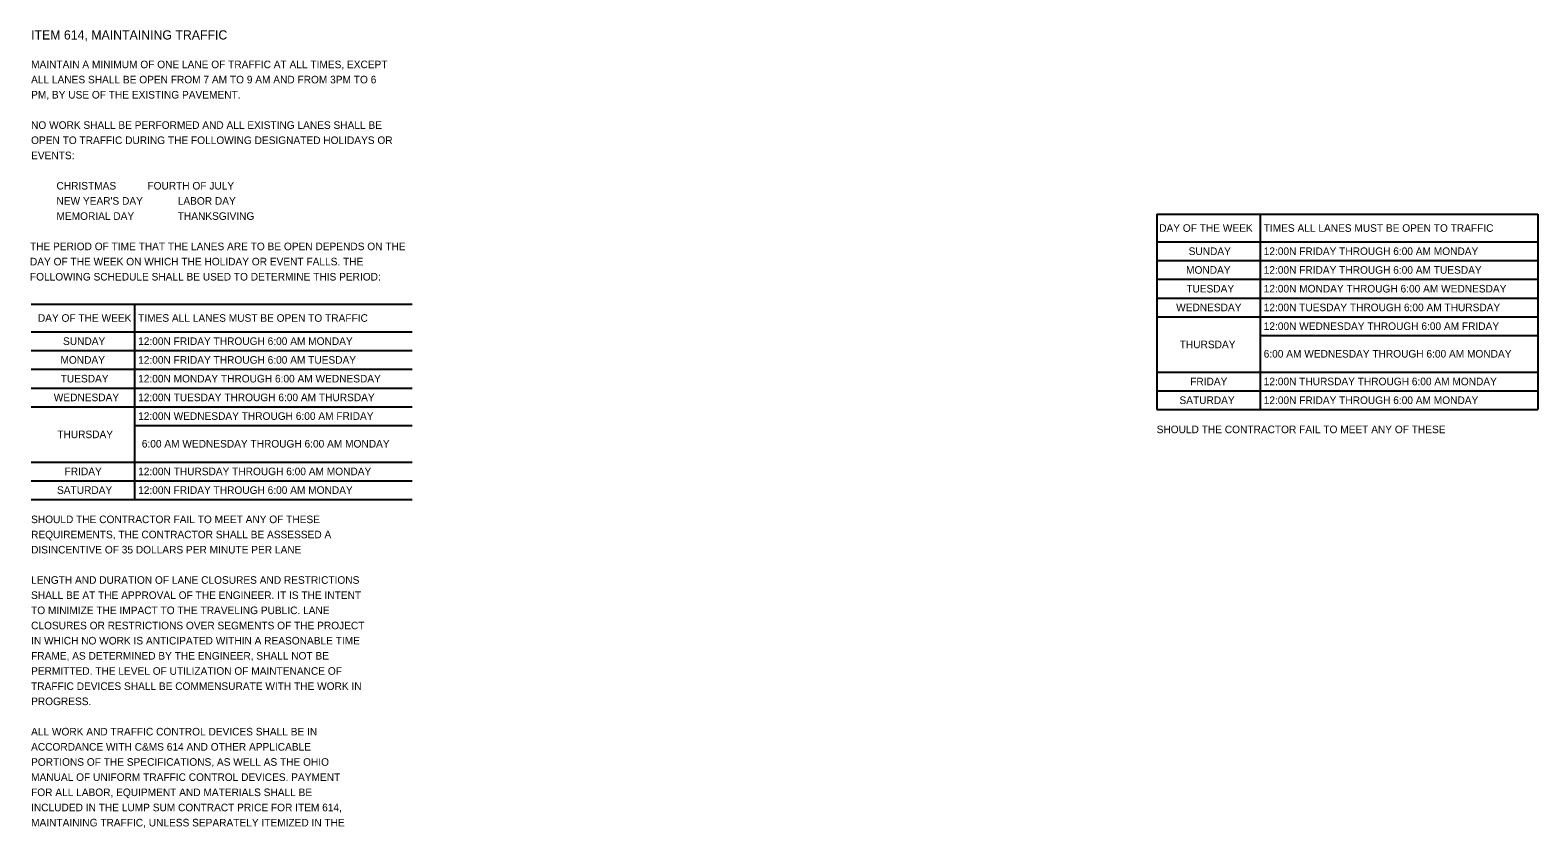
# Model space of a CAD drawing. Extents: x -57 to 90, y -15 to 48.
# Drawn here: x -29.92 to -2.07, y 4.75 to 19.48 of the extents above; entities that cross this region are included whole.
import ezdxf

# ---------------------------------------------------------------- set-up
doc = ezdxf.new("R2010")
doc.units = 0
doc.layers.add('SH_Data', color=7, linetype='Continuous')
doc.layers.add('SH_Text', color=7, linetype='Continuous')

msp = doc.modelspace()

# ---------------------------------------------------------------- linework, layer by layer
at = {"layer": 'SH_Data'}
for p, q in [((-9.111, 16.084), (-2.07, 16.084)), ((-9.111, 16.084), (-9.111, 12.476)), ((-7.2, 16.084), (-7.2, 12.476)), ((-2.07, 16.084), (-2.07, 12.476)), ((-9.111, 15.573), (-2.07, 15.573)), ((-9.111, 15.227), (-2.07, 15.227)), ((-9.111, 14.881), (-2.07, 14.881)), ((-9.111, 14.535), (-2.07, 14.535)), ((-29.903, 14.423), (-22.862, 14.423)), ((-27.992, 14.423), (-27.992, 10.816)), ((-27.992, 14.423), (-27.992, 10.816)), ((-9.111, 14.189), (-2.07, 14.189)), ((-29.903, 13.912), (-22.862, 13.912)), ((-29.903, 13.912), (-22.862, 13.912)), ((-7.2, 13.844), (-2.07, 13.844)), ((-29.903, 13.566), (-22.862, 13.566)), ((-29.903, 13.566), (-22.862, 13.566)), ((-29.903, 13.22), (-22.862, 13.22)), ((-29.903, 13.22), (-22.862, 13.22)), ((-9.111, 13.168), (-2.07, 13.168)), ((-29.903, 12.874), (-22.862, 12.874)), ((-29.903, 12.874), (-22.862, 12.874)), ((-9.111, 12.822), (-2.07, 12.822)), ((-29.903, 12.529), (-22.862, 12.529)), ((-29.903, 12.529), (-22.862, 12.529)), ((-9.111, 12.476), (-2.07, 12.476)), ((-27.992, 12.183), (-22.862, 12.183)), ((-27.992, 12.183), (-22.862, 12.183)), ((-29.903, 11.507), (-22.862, 11.507)), ((-29.903, 11.507), (-22.862, 11.507)), ((-29.903, 11.161), (-22.862, 11.161)), ((-29.903, 11.161), (-22.862, 11.161)), ((-29.903, 10.816), (-22.862, 10.816)), ((-29.903, 10.816), (-22.862, 10.816))]:
    msp.add_line(p, q, dxfattribs=at)

# ---------------------------------------------------------------- texts
at = {"layer": 'SH_Text'}
for s, height, p in [('ITEM 614, MAINTAINING TRAFFIC', 0.17, (-29.903, 19.309)), ('MAINTAIN A MINIMUM OF ONE LANE OF TRAFFIC AT ALL TIMES, EXCEPT ', 0.14, (-29.903, 18.779)), ('ALL LANES SHALL BE OPEN FROM 7 AM TO 9 AM AND FROM 3PM TO 6 ', 0.14, (-29.903, 18.499)), ('PM, BY USE OF THE EXISTING PAVEMENT.', 0.14, (-29.903, 18.219)), ('NO WORK SHALL BE PERFORMED AND ALL EXISTING LANES SHALL BE ', 0.14, (-29.903, 17.659)), ('OPEN TO TRAFFIC DURING THE FOLLOWING DESIGNATED HOLIDAYS OR ', 0.14, (-29.903, 17.379)), ('EVENTS:', 0.14, (-29.903, 17.099)), ('CHRISTMAS', 0.14, (-29.434, 16.539)), ('FOURTH OF JULY', 0.14, (-27.754, 16.539)), ("NEW YEAR'S DAY", 0.14, (-29.434, 16.259)), ('LABOR DAY', 0.14, (-27.194, 16.259)), ('MEMORIAL DAY', 0.14, (-29.434, 15.979)), ('THANKSGIVING', 0.14, (-27.194, 15.979)), ('DAY OF THE WEEK', 0.14, (-9.064, 15.758)), ('TIMES ALL LANES MUST BE OPEN TO TRAFFIC', 0.14, (-7.134, 15.758)), ('THE PERIOD OF TIME THAT THE LANES ARE TO BE OPEN DEPENDS ON THE ', 0.14, (-29.924, 15.419)), ('SUNDAY', 0.14, (-8.521, 15.33)), ('12:00N FRIDAY THROUGH 6:00 AM MONDAY', 0.14, (-7.134, 15.33)), ('DAY OF THE WEEK ON WHICH THE HOLIDAY OR EVENT FALLS. THE ', 0.14, (-29.924, 15.139)), ('MONDAY', 0.14, (-8.568, 14.984)), ('12:00N FRIDAY THROUGH 6:00 AM TUESDAY', 0.14, (-7.134, 14.984)), ('FOLLOWING SCHEDULE SHALL BE USED TO DETERMINE THIS PERIOD:', 0.14, (-29.924, 14.859)), ('TUESDAY', 0.14, (-8.564, 14.638)), ('12:00N MONDAY THROUGH 6:00 AM WEDNESDAY', 0.14, (-7.134, 14.638)), ('DAY OF THE WEEK', 0.14, (-29.777, 14.097)), ('TIMES ALL LANES MUST BE OPEN TO TRAFFIC', 0.14, (-27.926, 14.097)), ('WEDNESDAY', 0.14, (-8.751, 14.292)), ('12:00N TUESDAY THROUGH 6:00 AM THURSDAY', 0.14, (-7.134, 14.292)), ('12:00N WEDNESDAY THROUGH 6:00 AM FRIDAY', 0.14, (-7.134, 13.946)), ('SUNDAY', 0.14, (-29.313, 13.669)), ('12:00N FRIDAY THROUGH 6:00 AM MONDAY', 0.14, (-27.926, 13.669)), ('THURSDAY', 0.14, (-8.685, 13.609)), ('MONDAY', 0.14, (-29.36, 13.323)), ('12:00N FRIDAY THROUGH 6:00 AM TUESDAY', 0.14, (-27.926, 13.323)), ('6:00 AM WEDNESDAY THROUGH 6:00 AM MONDAY', 0.14, (-7.134, 13.436)), ('TUESDAY', 0.14, (-29.356, 12.977)), ('12:00N MONDAY THROUGH 6:00 AM WEDNESDAY', 0.14, (-27.926, 12.977)), ('FRIDAY', 0.14, (-8.492, 12.925)), ('12:00N THURSDAY THROUGH 6:00 AM MONDAY', 0.14, (-7.134, 12.925)), ('WEDNESDAY', 0.14, (-29.484, 12.631)), ('12:00N TUESDAY THROUGH 6:00 AM THURSDAY', 0.14, (-27.926, 12.631)), ('SATURDAY', 0.14, (-8.69, 12.579)), ('12:00N FRIDAY THROUGH 6:00 AM MONDAY', 0.14, (-7.134, 12.579)), ('12:00N WEDNESDAY THROUGH 6:00 AM FRIDAY', 0.14, (-27.926, 12.286)), ('THURSDAY', 0.14, (-29.419, 11.948)), ('SHOULD THE CONTRACTOR FAIL TO MEET ANY OF THESE', 0.14, (-9.111, 12.04)), ('6:00 AM WEDNESDAY THROUGH 6:00 AM MONDAY', 0.14, (-27.858, 11.775)), ('FRIDAY', 0.14, (-29.284, 11.264)), ('12:00N THURSDAY THROUGH 6:00 AM MONDAY', 0.14, (-27.926, 11.264)), ('SATURDAY', 0.14, (-29.424, 10.919)), ('12:00N FRIDAY THROUGH 6:00 AM MONDAY', 0.14, (-27.926, 10.919)), ('SHOULD THE CONTRACTOR FAIL TO MEET ANY OF THESE', 0.14, (-29.903, 10.379)), ('REQUIREMENTS, THE CONTRACTOR SHALL BE ASSESSED A', 0.14, (-29.903, 10.099)), ('DISINCENTIVE OF 35 DOLLARS PER MINUTE PER LANE', 0.14, (-29.903, 9.819)), ('LENGTH AND DURATION OF LANE CLOSURES AND RESTRICTIONS', 0.14, (-29.903, 9.259)), ('SHALL BE AT THE APPROVAL OF THE ENGINEER. IT IS THE INTENT', 0.14, (-29.903, 8.979)), ('TO MINIMIZE THE IMPACT TO THE TRAVELING PUBLIC. LANE', 0.14, (-29.903, 8.699)), ('CLOSURES OR RESTRICTIONS OVER SEGMENTS OF THE PROJECT', 0.14, (-29.903, 8.419)), ('IN WHICH NO WORK IS ANTICIPATED WITHIN A REASONABLE TIME', 0.14, (-29.903, 8.139)), ('FRAME, AS DETERMINED BY THE ENGINEER, SHALL NOT BE', 0.14, (-29.903, 7.859)), ('PERMITTED. THE LEVEL OF UTILIZATION OF MAINTENANCE OF', 0.14, (-29.903, 7.579)), ('TRAFFIC DEVICES SHALL BE COMMENSURATE WITH THE WORK IN', 0.14, (-29.903, 7.299)), ('PROGRESS.', 0.14, (-29.903, 7.019)), ('ALL WORK AND TRAFFIC CONTROL DEVICES SHALL BE IN', 0.14, (-29.903, 6.459)), ('ACCORDANCE WITH C&MS 614 AND OTHER APPLICABLE', 0.14, (-29.903, 6.179)), ('PORTIONS OF THE SPECIFICATIONS, AS WELL AS THE OHIO', 0.14, (-29.903, 5.899)), ('MANUAL OF UNIFORM TRAFFIC CONTROL DEVICES. PAYMENT', 0.14, (-29.903, 5.619)), ('FOR ALL LABOR, EQUIPMENT AND MATERIALS SHALL BE', 0.14, (-29.903, 5.339)), ('INCLUDED IN THE LUMP SUM CONTRACT PRICE FOR ITEM 614,', 0.14, (-29.903, 5.059)), ('MAINTAINING TRAFFIC, UNLESS SEPARATELY ITEMIZED IN THE', 0.14, (-29.903, 4.779))]:
    msp.add_text(s, height=height, dxfattribs=at).set_placement(p)

doc.saveas('drawing.dxf')
